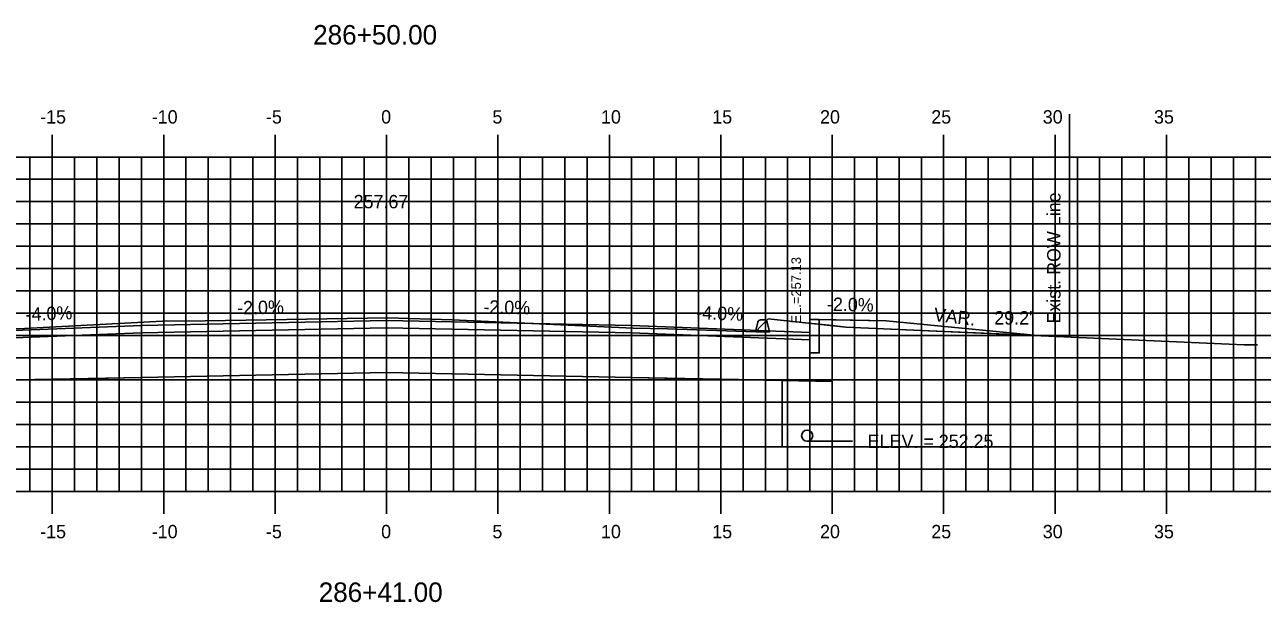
# Model space of a CAD drawing. Extents: x 856903 to 857073, y 366268 to 366378.
# Drawn here: x 856969.5 to 857025.1, y 366322.3 to 366348.2 of the extents above; entities that cross this region are included whole.
import ezdxf

# ---------------------------------------------------------------- set-up
doc = ezdxf.new("R2010")
doc.units = 0
for name, color, linetype in [('ANNOTATION', 7, 'Continuous'), ('D_Curb_Type_1_Rt', 7, 'Continuous'), ('D_Roadway_Centerline_Text', 7, 'Continuous'), ('D_Roadway_Edge_Shoulder', 7, 'Continuous'), ('D_Roadway_FinishedGrade', 7, 'Continuous'), ('D_Roadway_SubGrade', 7, 'Continuous'), ('D_Text_Standard', 7, 'Continuous'), ('E_ROW_Line', 7, 'Continuous'), ('H_V ANNOTATION', 7, 'Continuous'), ('JUNK COM EXC', 7, 'Continuous'), ('JUNK FILL', 7, 'Continuous'), ('junk strct exc', 7, 'Continuous'), ('MAJOR', 7, 'Continuous'), ('MINOR', 7, 'Continuous'), ('PDRAIN', 7, 'Continuous'), ('S_Curb_Type_3', 7, 'Continuous'), ('S_Roadway_Centerline', 7, 'Continuous')]:
    doc.layers.add(name, color=color, linetype=linetype)

msp = doc.modelspace()

# ---------------------------------------------------------------- linework, layer by layer
at = {"layer": 'D_Curb_Type_1_Rt'}
msp.add_lwpolyline([(857005.2, 366334.947), (857005.2, 366333.447), (857004.784, 366333.447), (857004.784, 366334.947)], close=True, dxfattribs=at)
at = {"layer": 'D_Roadway_Edge_Shoulder'}
msp.add_line((857004.785, 366334.363), (857004.784, 366334.03), dxfattribs=at)
msp.add_lwpolyline([(856966.784, 366334.363), (856974.784, 366334.683), (856985.784, 366334.903), (856996.784, 366334.683), (857004.785, 366334.363)], dxfattribs=at)
at = {"layer": 'D_Roadway_FinishedGrade'}
for points in [[(857005.201, 366334.946), (857008.201, 366334.886)], [(857008.201, 366334.886), (857014.999, 366334.227)]]:
    msp.add_lwpolyline(points, dxfattribs=at)
at = {"layer": 'D_Roadway_SubGrade'}
for points in [[(856974.784, 366332.35), (856974.784, 366334.35), (856985.784, 366334.57), (856996.784, 366334.35), (856996.784, 366332.35), (856985.784, 366332.57)], [(856974.784, 366334.35), (856966.784, 366334.03), (856966.784, 366332.19), (856974.784, 366332.35)], [(856996.784, 366334.35), (857004.784, 366334.03), (857004.784, 366332.19), (856996.784, 366332.35)]]:
    msp.add_lwpolyline(points, close=True, dxfattribs=at)
msp.add_lwpolyline([(857005.784, 366334.935), (857005.784, 366332.17), (857004.784, 366332.19)], dxfattribs=at)
at = {"layer": 'D_Text_Standard'}
msp.add_lwpolyline([(857004.659, 366329.486), (857006.016, 366329.486), (857006.696, 366329.486)], dxfattribs=at)
at = {"layer": 'E_ROW_Line'}
msp.add_line((857016.428, 366334.164), (857016.428, 366344.164), dxfattribs=at)
at = {"layer": 'JUNK COM EXC'}
msp.add_lwpolyline([(857005.784, 366334.674), (857004.443, 366334.819), (857002.913, 366334.984), (857002.611, 366334.676), (857002.347, 366334.388), (856998.4, 366334.53), (856996.854, 366334.558), (856988.735, 366334.939), (856985.845, 366335.02), (856977.64, 366334.888), (856975.733, 366334.868), (856969.543, 366334.552), (856968.014, 366334.513), (856967.076, 366334.658), (856966.809, 366334.862), (856966.744, 366334.828), (856965.784, 366334.855), (856965.784, 366332.17), (856974.784, 366332.35), (856985.784, 366332.57), (856996.784, 366332.35), (857005.784, 366332.17), (857005.784, 366334.674)], dxfattribs=at)
at = {"layer": 'JUNK FILL'}
msp.add_lwpolyline([(857005.784, 366334.674), (857006.394, 366334.608), (857009.441, 366334.473), (857014.999, 366334.227), (857008.201, 366334.886), (857005.784, 366334.935)], close=True, dxfattribs=at)
at = {"layer": 'junk strct exc'}
msp.add_lwpolyline([(857003.534, 366332.215), (857003.534, 366329.236), (857005.784, 366329.236), (857005.784, 366332.17)], close=True, dxfattribs=at)
at = {"layer": 'MAJOR'}
for p, q in [((856970.784, 366343.238), (856970.784, 366342.236)), ((856975.784, 366343.238), (856975.784, 366342.236)), ((856980.784, 366343.238), (856980.784, 366342.236)), ((856985.784, 366343.238), (856985.784, 366342.236)), ((856990.784, 366343.238), (856990.784, 366342.236)), ((856995.784, 366343.238), (856995.784, 366342.236)), ((857000.784, 366343.238), (857000.784, 366342.236)), ((857005.784, 366343.238), (857005.784, 366342.236)), ((857010.784, 366343.238), (857010.784, 366342.236)), ((857015.784, 366343.238), (857015.784, 366342.236)), ((857020.784, 366343.238), (857020.784, 366342.236)), ((856915.784, 366342.236), (857055.784, 366342.236)), ((856915.784, 366342.236), (857055.784, 366342.236)), ((856970.784, 366327.236), (856970.784, 366342.236)), ((856975.784, 366327.236), (856975.784, 366342.236)), ((856980.784, 366327.236), (856980.784, 366342.236)), ((856985.784, 366327.236), (856985.784, 366342.236)), ((856990.784, 366327.236), (856990.784, 366342.236)), ((856995.784, 366327.236), (856995.784, 366342.236)), ((857000.784, 366327.236), (857000.784, 366342.236)), ((857005.784, 366327.236), (857005.784, 366342.236)), ((857010.784, 366327.236), (857010.784, 366342.236)), ((857015.784, 366327.236), (857015.784, 366342.236)), ((857020.784, 366327.236), (857020.784, 366342.236)), ((856915.784, 366337.236), (857055.784, 366337.236)), ((856915.784, 366332.236), (857055.784, 366332.236)), ((856915.784, 366327.236), (857055.784, 366327.236)), ((856915.784, 366327.236), (857055.784, 366327.236)), ((856970.784, 366326.234), (856970.784, 366327.236)), ((856975.784, 366326.234), (856975.784, 366327.236)), ((856980.784, 366326.234), (856980.784, 366327.236)), ((856985.784, 366326.234), (856985.784, 366327.236)), ((856990.784, 366326.234), (856990.784, 366327.236)), ((856995.784, 366326.234), (856995.784, 366327.236)), ((857000.784, 366326.234), (857000.784, 366327.236)), ((857005.784, 366326.234), (857005.784, 366327.236)), ((857010.784, 366326.234), (857010.784, 366327.236)), ((857015.784, 366326.234), (857015.784, 366327.236)), ((857020.784, 366326.234), (857020.784, 366327.236))]:
    msp.add_line(p, q, dxfattribs=at)
at = {"layer": 'MINOR'}
for p, q in [((856969.784, 366327.236), (856969.784, 366342.236)), ((856971.784, 366327.236), (856971.784, 366342.236)), ((856972.784, 366327.236), (856972.784, 366342.236)), ((856973.784, 366327.236), (856973.784, 366342.236)), ((856974.784, 366327.236), (856974.784, 366342.236)), ((856976.784, 366327.236), (856976.784, 366342.236)), ((856977.784, 366327.236), (856977.784, 366342.236)), ((856978.784, 366327.236), (856978.784, 366342.236)), ((856979.784, 366327.236), (856979.784, 366342.236)), ((856981.784, 366327.236), (856981.784, 366342.236)), ((856982.784, 366327.236), (856982.784, 366342.236)), ((856983.784, 366327.236), (856983.784, 366342.236)), ((856984.784, 366327.236), (856984.784, 366342.236)), ((856986.784, 366327.236), (856986.784, 366342.236)), ((856987.784, 366327.236), (856987.784, 366342.236)), ((856988.784, 366327.236), (856988.784, 366342.236)), ((856989.784, 366327.236), (856989.784, 366342.236)), ((856991.784, 366327.236), (856991.784, 366342.236)), ((856992.784, 366327.236), (856992.784, 366342.236)), ((856993.784, 366327.236), (856993.784, 366342.236)), ((856994.784, 366327.236), (856994.784, 366342.236)), ((856996.784, 366327.236), (856996.784, 366342.236)), ((856997.784, 366327.236), (856997.784, 366342.236)), ((856998.784, 366327.236), (856998.784, 366342.236)), ((856999.784, 366327.236), (856999.784, 366342.236)), ((857001.784, 366327.236), (857001.784, 366342.236)), ((857002.784, 366327.236), (857002.784, 366342.236)), ((857003.784, 366327.236), (857003.784, 366342.236)), ((857004.784, 366327.236), (857004.784, 366342.236)), ((857006.784, 366327.236), (857006.784, 366342.236)), ((857007.784, 366327.236), (857007.784, 366342.236)), ((857008.784, 366327.236), (857008.784, 366342.236)), ((857009.784, 366327.236), (857009.784, 366342.236)), ((857011.784, 366327.236), (857011.784, 366342.236)), ((857012.784, 366327.236), (857012.784, 366342.236)), ((857013.784, 366327.236), (857013.784, 366342.236)), ((857014.784, 366327.236), (857014.784, 366342.236)), ((857016.784, 366327.236), (857016.784, 366342.236)), ((857017.784, 366327.236), (857017.784, 366342.236)), ((857018.784, 366327.236), (857018.784, 366342.236)), ((857019.784, 366327.236), (857019.784, 366342.236)), ((857021.784, 366327.236), (857021.784, 366342.236)), ((857022.784, 366327.236), (857022.784, 366342.236)), ((857023.784, 366327.236), (857023.784, 366342.236)), ((857024.784, 366327.236), (857024.784, 366342.236)), ((856915.784, 366341.236), (857055.784, 366341.236)), ((856915.784, 366340.236), (857055.784, 366340.236)), ((856915.784, 366339.236), (857055.784, 366339.236)), ((856915.784, 366338.236), (857055.784, 366338.236)), ((856915.784, 366336.236), (857055.784, 366336.236)), ((856915.784, 366335.236), (857055.784, 366335.236)), ((856915.784, 366334.236), (857055.784, 366334.236)), ((856915.784, 366333.236), (857055.784, 366333.236)), ((856915.784, 366331.236), (857055.784, 366331.236)), ((856915.784, 366330.236), (857055.784, 366330.236)), ((856915.784, 366329.236), (857055.784, 366329.236)), ((856915.784, 366328.236), (857055.784, 366328.236))]:
    msp.add_line(p, q, dxfattribs=at)
at = {"layer": 'PDRAIN'}
msp.add_lwpolyline([(857003.534, 366332.215), (857003.534, 366329.236), (857005.784, 366329.236), (857005.784, 366332.17)], dxfattribs=at)
msp.add_circle((857004.659, 366329.736), 0.25, dxfattribs=at)
at = {"layer": 'S_Curb_Type_3'}
for points in [[(857002.87, 366334.832), (857002.972, 366334.388), (857002.347, 366334.388), (857002.45, 366334.832)], [(857002.572, 366334.929), (857002.748, 366334.929)]]:
    msp.add_lwpolyline(points, dxfattribs=at)
for centre, start, end in [((857002.572, 366334.804), 90, 167.0054), ((857002.748, 366334.804), 12.9946, 90)]:
    msp.add_arc(centre, 0.125, start, end, dxfattribs=at)
at = {"layer": 'S_Roadway_Centerline'}
msp.add_lwpolyline([(856969.543, 366334.552), (856975.733, 366334.868), (856977.64, 366334.888), (856985.845, 366335.02), (856988.735, 366334.939), (856996.854, 366334.558), (856998.4, 366334.53), (857002.347, 366334.388), (857002.611, 366334.676), (857002.913, 366334.984), (857004.443, 366334.819), (857006.394, 366334.608), (857023.603, 366333.846), (857024.271, 366333.818), (857024.874, 366333.815)], dxfattribs=at)

# ---------------------------------------------------------------- texts
at = {"layer": 'ANNOTATION'}
for s, rotation, p in [('-2.0%', 1.1458, (856979.087, 366335.17)), ('-2.0%', 358.8542, (856990.127, 366335.217)), ('-2.0%', 358.8542, (857005.544, 366335.34)), ('-4.0%', 2.2906, (856969.6, 366334.877)), ('-4.0%', 357.7094, (856999.678, 366334.969)), ('VAR.', 353.2778, (857010.317, 366334.884))]:
    msp.add_text(s, height=0.6, rotation=rotation, dxfattribs=at).set_placement(p)
at = {"layer": 'D_Roadway_Centerline_Text'}
msp.add_text('257.67', height=0.6, dxfattribs=at).set_placement((856984.307, 366339.935))
at = {"layer": 'D_Text_Standard'}
msp.add_text(' EL.=257.13', height=0.4335, rotation=90, dxfattribs=at).set_placement((857004.382, 366334.608))
for s, p in [("29.2'", (857013.056, 366334.723)), ('ELEV. = 252.25', (857007.376, 366329.186))]:
    msp.add_text(s, height=0.6, dxfattribs=at).set_placement(p)
at = {"layer": 'E_ROW_Line'}
msp.add_text('Exist. ROW Line', height=0.6, rotation=90, dxfattribs=at).set_placement((857016.028, 366334.764))
at = {"layer": 'H_V ANNOTATION'}
for s, height, p in [('286+50.00', 0.875, (856982.491, 366347.28)), ('-15', 0.6, (856970.241, 366343.736)), ('-10', 0.6, (856975.249, 366343.736)), ('-5', 0.6, (856980.375, 366343.736)), ('0', 0.6, (856985.543, 366343.736)), ('5', 0.6, (856990.535, 366343.736)), ('10', 0.6, (856995.409, 366343.736)), ('15', 0.6, (857000.401, 366343.736)), ('20', 0.6, (857005.238, 366343.736)), ('25', 0.6, (857010.23, 366343.736)), ('30', 0.6, (857015.233, 366343.736)), ('35', 0.6, (857020.225, 366343.736)), ('-15', 0.6, (856970.241, 366325.136)), ('-10', 0.6, (856975.249, 366325.136)), ('-5', 0.6, (856980.375, 366325.136)), ('0', 0.6, (856985.543, 366325.136)), ('5', 0.6, (856990.535, 366325.136)), ('10', 0.6, (856995.409, 366325.136)), ('15', 0.6, (857000.401, 366325.136)), ('20', 0.6, (857005.238, 366325.136)), ('25', 0.6, (857010.23, 366325.136)), ('30', 0.6, (857015.233, 366325.136)), ('35', 0.6, (857020.225, 366325.136)), ('286+41.00', 0.875, (856982.741, 366322.28))]:
    msp.add_text(s, height=height, dxfattribs=at).set_placement(p)
at = {"layer": 'S_Roadway_Centerline'}
for s, p in [('C', (856985.84, 366335.02)), ('L', (856985.845, 366335.012))]:
    msp.add_text(s, height=0.0146, dxfattribs=at).set_placement(p)

doc.saveas('drawing.dxf')
